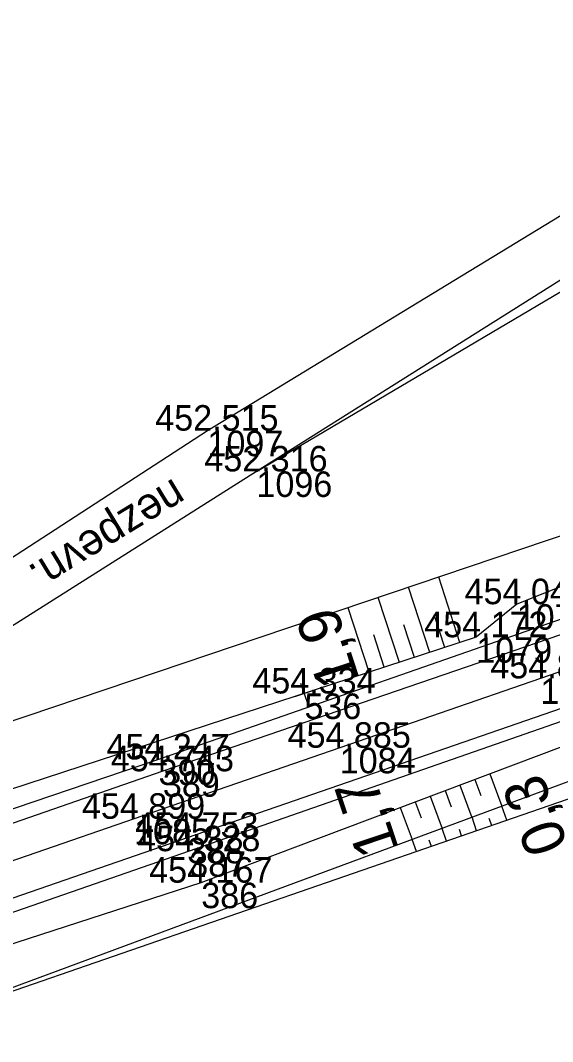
# Model space of a CAD drawing. Extents: x -751615 to -750797, y -1114905 to -1114561.
# Drawn here: x -751575.2 to -751550.15, y -1114845.39 to -1114797.38 of the extents above; entities that cross this region are included whole.
import ezdxf

# ---------------------------------------------------------------- set-up
doc = ezdxf.new("R2010")
doc.units = 0
for name, color, linetype in [('Vrstva 1', 7, 'Continuous'), ('Vrstva 4', 7, 'Continuous'), ('Vrstva 48', 7, 'Continuous'), ('Vrstva 49', 7, 'Continuous'), ('Vrstva 51', 7, 'Continuous'), ('Vrstva 60', 7, 'Continuous'), ('Vrstva 61', 7, 'Continuous'), ('Vrstva 7', 7, 'Continuous')]:
    doc.layers.add(name, color=color, linetype=linetype)

msp = doc.modelspace()

# ---------------------------------------------------------------- linework, layer by layer
at = {"layer": 'Vrstva 1'}
msp.add_lwpolyline([(-751416.742, -1114782.09), (-751426.633, -1114785.503), (-751435.883, -1114788.699), (-751445.473, -1114792.007), (-751455.331, -1114795.406), (-751464.93, -1114798.717), (-751474.392, -1114801.982), (-751484.022, -1114805.308), (-751487.237, -1114806.416), (-751493.406, -1114808.538), (-751502.885, -1114811.809), (-751512.358, -1114815.079), (-751523.744, -1114819.014), (-751530.663, -1114821.401), (-751541.116, -1114825.002), (-751550.726, -1114828.317), (-751560.172, -1114831.578), (-751569.853, -1114834.918), (-751579.125, -1114838.113), (-751588.602, -1114841.381)], dxfattribs=at)
at = {"layer": 'Vrstva 4'}
for points in [[(-751531.222, -1114820.049), (-751532.411, -1114819.814), (-751547.631, -1114824.789), (-751568.7, -1114832.128), (-751588.868, -1114838.968)], [(-751531.222, -1114820.049), (-751547.578, -1114825.515), (-751568.497, -1114832.683), (-751588.528, -1114839.629)], [(-751529.854, -1114822.836), (-751546.799, -1114828.717), (-751567.35, -1114835.812), (-751587.5, -1114842.776)], [(-751529.854, -1114822.836), (-751530.62, -1114823.702), (-751546.636, -1114829.261), (-751567.254, -1114836.441), (-751587.282, -1114843.385)]]:
    msp.add_lwpolyline(points, dxfattribs=at)
at = {"layer": 'Vrstva 48'}
for p, q in [((-751554.511, -1114826.632), (-751555.515, -1114823.554)), ((-751555.936, -1114827.098), (-751556.937, -1114824.034)), ((-751557.362, -1114827.563), (-751558.358, -1114824.513)), ((-751558.788, -1114828.028), (-751559.779, -1114824.992)), ((-751555.224, -1114826.865), (-751555.725, -1114825.329)), ((-751556.649, -1114827.33), (-751557.148, -1114825.802)), ((-751558.075, -1114827.796), (-751558.572, -1114826.274)), ((-751553.109, -1114832.802), (-751552.544, -1114834.329)), ((-751554.513, -1114833.331), (-751553.951, -1114834.85)), ((-751553.811, -1114833.066), (-751553.529, -1114833.828)), ((-751555.916, -1114833.86), (-751555.357, -1114835.371)), ((-751555.215, -1114833.595), (-751554.934, -1114834.353)), ((-751557.32, -1114834.389), (-751556.764, -1114835.891)), ((-751556.618, -1114834.124), (-751556.34, -1114834.877)), ((-751552.309, -1114834.99), (-751552.538, -1114834.327)), ((-751553.727, -1114835.48), (-751553.945, -1114834.848)), ((-751553.018, -1114835.235), (-751553.13, -1114834.911)), ((-751555.145, -1114835.969), (-751555.352, -1114835.369)), ((-751554.436, -1114835.725), (-751554.542, -1114835.416)), ((-751556.563, -1114836.459), (-751556.759, -1114835.889)), ((-751555.854, -1114836.214), (-751555.955, -1114835.921))]:
    msp.add_line(p, q, dxfattribs=at)
at = {"layer": 'Vrstva 49'}
msp.add_line((-751534.993, -1114829.012), (-751582.438, -1114845.392), dxfattribs=at)
for points in [[(-751535.601, -1114808.255), (-751541.69, -1114804.508), (-751564.092, -1114818.587)], [(-751564.092, -1114818.587), (-751543.018, -1114806.139), (-751536.934, -1114809.473), (-751533.922, -1114815.785), (-751539.386, -1114818.117), (-751585.925, -1114833.806), (-751595.742, -1114835.716)], [(-751535.601, -1114808.255), (-751531.347, -1114816.521), (-751539.042, -1114819.748), (-751551.843, -1114824.829), (-751553.747, -1114826.383), (-751585.03, -1114836.593)], [(-751586.983, -1114844.483), (-751566.691, -1114837.92), (-751546.322, -1114830.244), (-751529.778, -1114824.115), (-751528.71, -1114826.495)], [(-751535.416, -1114827.991), (-751582.438, -1114845.392)]]:
    msp.add_lwpolyline(points, dxfattribs=at)
at = {"layer": 'Vrstva 51'}
msp.add_lwpolyline([(-751609.483, -1114825.691), (-751605.933, -1114829.205), (-751594.773, -1114830.558), (-751581.97, -1114826.747), (-751566.399, -1114816.669), (-751540.967, -1114801.189), (-751532.595, -1114806.752), (-751528.368, -1114813.336), (-751525.848, -1114818.694), (-751529.358, -1114819.936), (-751530.249, -1114815.352), (-751535.601, -1114808.255), (-751541.69, -1114804.508), (-751564.092, -1114818.587), (-751580.945, -1114829.238), (-751594.664, -1114833.383), (-751607.051, -1114832.427), (-751612.458, -1114827.357)], dxfattribs=at)
at = {"layer": 'Vrstva 60'}
for p, q in [((-751566.399, -1114816.669), (-751566.399, -1114816.669)), ((-751564.092, -1114818.587), (-751564.092, -1114818.587)), ((-751551.843, -1114824.829), (-751551.843, -1114824.829)), ((-751553.747, -1114826.383), (-751553.747, -1114826.383)), ((-751550.726, -1114828.317), (-751550.726, -1114828.317)), ((-751561.833, -1114829.027), (-751561.833, -1114829.027)), ((-751560.172, -1114831.578), (-751560.172, -1114831.578)), ((-751568.7, -1114832.128), (-751568.7, -1114832.128)), ((-751568.497, -1114832.683), (-751568.497, -1114832.683)), ((-751569.853, -1114834.918), (-751569.853, -1114834.918)), ((-751567.35, -1114835.812), (-751567.35, -1114835.812)), ((-751567.254, -1114836.441), (-751567.254, -1114836.441)), ((-751566.691, -1114837.92), (-751566.691, -1114837.92))]:
    msp.add_line(p, q, dxfattribs=at)
at = {"layer": 'Vrstva 7'}
for p, q in [((-751561.67, -1114829.5), (-751561.996, -1114828.554)), ((-751561.36, -1114828.864), (-751562.306, -1114829.19))]:
    msp.add_line(p, q, dxfattribs=at)

# ---------------------------------------------------------------- texts
at = {"layer": 'Vrstva 48'}
for s, rotation, p in [('1,9', 108.0754, (-751559.221, -1114828.364)), ('0,3', 110.3075, (-751549.402, -1114836.169)), ('1,7', 108.4718, (-751557.377, -1114836.323))]:
    msp.add_text(s, height=2, rotation=rotation, dxfattribs=at).set_placement(p)
at = {"layer": 'Vrstva 51'}
msp.add_text('nezpevn.', height=1.5, rotation=211.3281, dxfattribs=at).set_placement((-751567.985, -1114818.875))
at = {"layer": 'Vrstva 60'}
for s, p in [('1097', (-751566.399, -1114817.869)), ('1096', (-751564.092, -1114819.787)), ('1078', (-751551.843, -1114826.029)), ('1079', (-751553.747, -1114827.583)), ('1083', (-751550.726, -1114829.517)), ('536', (-751561.833, -1114830.227)), ('1084', (-751560.172, -1114832.778)), ('390', (-751568.7, -1114833.328)), ('389', (-751568.497, -1114833.883)), ('1085', (-751569.853, -1114836.118)), ('388', (-751567.35, -1114837.012)), ('387', (-751567.254, -1114837.641)), ('386', (-751566.691, -1114839.12))]:
    msp.add_text(s, height=1.2, dxfattribs=at).set_placement(p)
at = {"layer": 'Vrstva 61'}
for s, p in [('452.515', (-751568.855, -1114816.669)), ('452.316', (-751566.544, -1114818.587)), ('454.044', (-751554.294, -1114824.829)), ('454.172', (-751556.195, -1114826.383)), ('454.871', (-751553.083, -1114828.317)), ('454.334', (-751564.284, -1114829.027)), ('454.885', (-751562.628, -1114831.578)), ('454.247', (-751571.152, -1114832.128)), ('454.743', (-751570.949, -1114832.683)), ('454.899', (-751572.307, -1114834.918)), ('454.753', (-751569.802, -1114835.812)), ('454.328', (-751569.708, -1114836.441)), ('454.167', (-751569.143, -1114837.92))]:
    msp.add_text(s, height=1.2, dxfattribs=at).set_placement(p)

doc.saveas('drawing.dxf')
